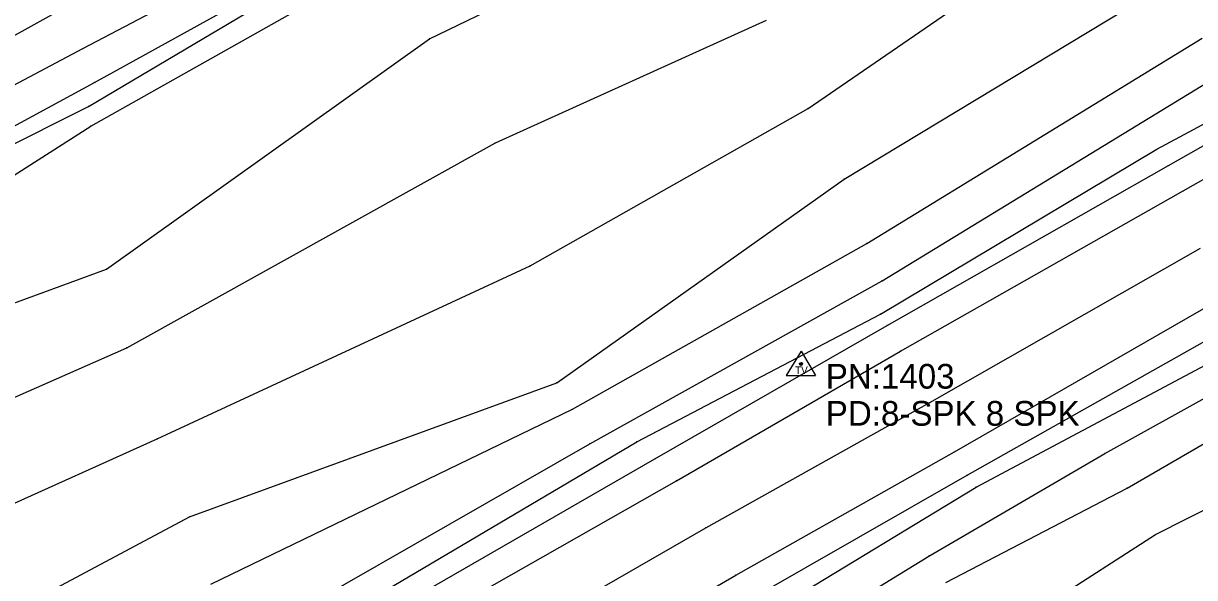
# Model space of a CAD drawing. Extents: x 1419505 to 1434054, y 1956910 to 1968644.
# Drawn here: x 1419625.5 to 1419862.1, y 1957056.8 to 1957168.8 of the extents above; entities that cross this region are included whole.
import ezdxf

# ---------------------------------------------------------------- set-up
doc = ezdxf.new("R2010")
doc.units = 0
for name, color, linetype in [('S_BREAKLINE', 7, 'Continuous'), ('S_DITCHLINE', 7, 'Continuous'), ('S_EDGE_PAVEMENT', 7, 'Continuous'), ('S_GRD_PT_SYM', 7, 'Continuous'), ('S_PAVEMENT_CROWN', 7, 'Continuous'), ('S_RDW_PT_SYM', 7, 'Continuous'), ('S_SECONDARY_CTL', 7, 'Continuous'), ('S_SECONDARY_CTL_ANNOT', 7, 'Continuous'), ('S_SHOULDER', 7, 'Continuous')]:
    doc.layers.add(name, color=color, linetype=linetype)

msp = doc.modelspace()

# ---------------------------------------------------------------- linework, layer by layer
at = {"layer": 'S_BREAKLINE'}
for p, q in [((1419707.5523, 1957165.7068), (1419766.4661, 1957194.2126)), ((1419784.0202, 1957151.5969), (1419847.2843, 1957195.1117)), ((1419637.5618, 1957163.7107), (1419691.7063, 1957192.3615)), ((1419639.1459, 1957148.0477), (1419697.3476, 1957180.8438)), ((1419564.7571, 1957133.6557), (1419643.8152, 1957177.5796)), ((1419791.3307, 1957137.332), (1419859.2891, 1957178.4016)), ((1419720.9172, 1957144.6574), (1419775.6307, 1957169.476)), ((1419854.5158, 1957143.3884), (1419900.6558, 1957168.211)), ((1419642.2981, 1957119.1268), (1419707.5523, 1957165.7068)), ((1419795.917, 1957124.3391), (1419863.6694, 1957165.8298)), ((1419562.865, 1957124.2821), (1419637.5618, 1957163.7107)), ((1419799.0002, 1957116.8016), (1419868.6507, 1957159.3284)), ((1419727.8786, 1957119.8018), (1419784.0202, 1957151.5969)), ((1419579.448, 1957109.9562), (1419639.1459, 1957148.0477)), ((1419646.4093, 1957103.2218), (1419720.9172, 1957144.6574)), ((1419798.6452, 1957110.0602), (1419854.5158, 1957143.3884)), ((1419733.296, 1957096.1553), (1419791.3307, 1957137.332)), ((1419736.4682, 1957090.83), (1419795.917, 1957124.3391)), ((1419652.5397, 1957084.7986), (1419727.8786, 1957119.8018)), ((1419581.6462, 1957096.9554), (1419642.2981, 1957119.1268)), ((1419739.9154, 1957083.8165), (1419799.0002, 1957116.8016)), ((1419843.9531, 1957081.8294), (1419898.0706, 1957111.9563)), ((1419749.447, 1957084.2115), (1419798.6452, 1957110.0602)), ((1419594.165, 1957080.1863), (1419646.4093, 1957103.2218)), ((1419848.5054, 1957074.8589), (1419900.3037, 1957104.9299)), ((1419817.9884, 1957075.058), (1419869.3807, 1957102.4977)), ((1419659.0462, 1957069.0646), (1419733.296, 1957096.1553)), ((1419854.2418, 1957065.4553), (1419906.1381, 1957092.025)), ((1419663.4064, 1957055.4547), (1419736.4682, 1957090.83)), ((1419610.414, 1957065.8034), (1419652.5397, 1957084.7986)), ((1419692.1763, 1957050.3554), (1419749.447, 1957084.2115)), ((1419668.0437, 1957042.6419), (1419739.9154, 1957083.8165)), ((1419808.4198, 1957061.097), (1419843.9531, 1957081.8294)), ((1419773.6516, 1957048.1512), (1419817.9884, 1957075.058)), ((1419811.874, 1957055.7677), (1419848.5054, 1957074.8589)), ((1419622.4238, 1957049.4993), (1419659.0462, 1957069.0646)), ((1419819.8215, 1957043.3979), (1419854.2418, 1957065.4553)), ((1419773.3415, 1957039.6207), (1419808.4198, 1957061.097))]:
    msp.add_line(p, q, dxfattribs=at)
at = {"layer": 'S_DITCHLINE'}
for p, q in [((1419638.6598, 1957151.9969), (1419697.7777, 1957187.1132)), ((1419639.8549, 1957156.8702), (1419695.8855, 1957187.8332)), ((1419570.8935, 1957119.4708), (1419639.8549, 1957156.8702)), ((1419577.5279, 1957121.3749), (1419638.6598, 1957151.9969))]:
    msp.add_line(p, q, dxfattribs=at)
at = {"layer": 'S_EDGE_PAVEMENT'}
for p, q in [((1419859.8281, 1957134.9358), (1419904.819, 1957160.9415)), ((1419802.6874, 1957102.5727), (1419859.8281, 1957134.9358)), ((1419813.6421, 1957082.2014), (1419866.2125, 1957112.4424)), ((1419757.4445, 1957076.345), (1419802.6874, 1957102.5727)), ((1419769.4263, 1957057.2438), (1419813.6421, 1957082.2014)), ((1419697.4796, 1957042.2308), (1419757.4445, 1957076.345)), ((1419709.3334, 1957022.4906), (1419769.4263, 1957057.2438))]:
    msp.add_line(p, q, dxfattribs=at)
at = {"layer": 'S_GRD_PT_SYM'}
for points in [[(1419707.5523, 1957165.7068), (1419707.5523, 1957165.7568), (1419707.5523, 1957165.7068), (1419707.5023, 1957165.7068), (1419707.5523, 1957165.7068), (1419707.5523, 1957165.6568), (1419707.5523, 1957165.7068), (1419707.6023, 1957165.7068)], [(1419637.5618, 1957163.7107), (1419637.5618, 1957163.7607), (1419637.5618, 1957163.7107), (1419637.5118, 1957163.7107), (1419637.5618, 1957163.7107), (1419637.5618, 1957163.6607), (1419637.5618, 1957163.7107), (1419637.6118, 1957163.7107)], [(1419639.8549, 1957156.8702), (1419639.8549, 1957156.9202), (1419639.8549, 1957156.8702), (1419639.8049, 1957156.8702), (1419639.8549, 1957156.8702), (1419639.8549, 1957156.8202), (1419639.8549, 1957156.8702), (1419639.9049, 1957156.8702)], [(1419638.6598, 1957151.9969), (1419638.6598, 1957152.0469), (1419638.6598, 1957151.9969), (1419638.6098, 1957151.9969), (1419638.6598, 1957151.9969), (1419638.6598, 1957151.9469), (1419638.6598, 1957151.9969), (1419638.7098, 1957151.9969)], [(1419784.0202, 1957151.5969), (1419784.0202, 1957151.6469), (1419784.0202, 1957151.5969), (1419783.9702, 1957151.5969), (1419784.0202, 1957151.5969), (1419784.0202, 1957151.5469), (1419784.0202, 1957151.5969), (1419784.0702, 1957151.5969)], [(1419639.1459, 1957148.0477), (1419639.1459, 1957148.0977), (1419639.1459, 1957148.0477), (1419639.0959, 1957148.0477), (1419639.1459, 1957148.0477), (1419639.1459, 1957147.9977), (1419639.1459, 1957148.0477), (1419639.1959, 1957148.0477)], [(1419720.9172, 1957144.6574), (1419720.9172, 1957144.7074), (1419720.9172, 1957144.6574), (1419720.8672, 1957144.6574), (1419720.9172, 1957144.6574), (1419720.9172, 1957144.6074), (1419720.9172, 1957144.6574), (1419720.9672, 1957144.6574)], [(1419854.5158, 1957143.3884), (1419854.5158, 1957143.4384), (1419854.5158, 1957143.3884), (1419854.4658, 1957143.3884), (1419854.5158, 1957143.3884), (1419854.5158, 1957143.3384), (1419854.5158, 1957143.3884), (1419854.5658, 1957143.3884)], [(1419791.3307, 1957137.332), (1419791.3307, 1957137.382), (1419791.3307, 1957137.332), (1419791.2807, 1957137.332), (1419791.3307, 1957137.332), (1419791.3307, 1957137.282), (1419791.3307, 1957137.332), (1419791.3807, 1957137.332)], [(1419795.917, 1957124.3391), (1419795.917, 1957124.3891), (1419795.917, 1957124.3391), (1419795.867, 1957124.3391), (1419795.917, 1957124.3391), (1419795.917, 1957124.2891), (1419795.917, 1957124.3391), (1419795.967, 1957124.3391)], [(1419727.8786, 1957119.8018), (1419727.8786, 1957119.8518), (1419727.8786, 1957119.8018), (1419727.8286, 1957119.8018), (1419727.8786, 1957119.8018), (1419727.8786, 1957119.7518), (1419727.8786, 1957119.8018), (1419727.9286, 1957119.8018)], [(1419642.2981, 1957119.1268), (1419642.2981, 1957119.1768), (1419642.2981, 1957119.1268), (1419642.2481, 1957119.1268), (1419642.2981, 1957119.1268), (1419642.2981, 1957119.0768), (1419642.2981, 1957119.1268), (1419642.3481, 1957119.1268)], [(1419799.0002, 1957116.8016), (1419799.0002, 1957116.8516), (1419799.0002, 1957116.8016), (1419798.9502, 1957116.8016), (1419799.0002, 1957116.8016), (1419799.0002, 1957116.7516), (1419799.0002, 1957116.8016), (1419799.0502, 1957116.8016)], [(1419798.6452, 1957110.0602), (1419798.6452, 1957110.1102), (1419798.6452, 1957110.0602), (1419798.5952, 1957110.0602), (1419798.6452, 1957110.0602), (1419798.6452, 1957110.0102), (1419798.6452, 1957110.0602), (1419798.6952, 1957110.0602)], [(1419646.4093, 1957103.2218), (1419646.4093, 1957103.2718), (1419646.4093, 1957103.2218), (1419646.3593, 1957103.2218), (1419646.4093, 1957103.2218), (1419646.4093, 1957103.1718), (1419646.4093, 1957103.2218), (1419646.4593, 1957103.2218)], [(1419733.296, 1957096.1553), (1419733.296, 1957096.2053), (1419733.296, 1957096.1553), (1419733.246, 1957096.1553), (1419733.296, 1957096.1553), (1419733.296, 1957096.1053), (1419733.296, 1957096.1553), (1419733.346, 1957096.1553)], [(1419736.4682, 1957090.83), (1419736.4682, 1957090.88), (1419736.4682, 1957090.83), (1419736.4182, 1957090.83), (1419736.4682, 1957090.83), (1419736.4682, 1957090.78), (1419736.4682, 1957090.83), (1419736.5182, 1957090.83)], [(1419652.5397, 1957084.7986), (1419652.5397, 1957084.8486), (1419652.5397, 1957084.7986), (1419652.4897, 1957084.7986), (1419652.5397, 1957084.7986), (1419652.5397, 1957084.7486), (1419652.5397, 1957084.7986), (1419652.5897, 1957084.7986)], [(1419749.447, 1957084.2115), (1419749.447, 1957084.2615), (1419749.447, 1957084.2115), (1419749.397, 1957084.2115), (1419749.447, 1957084.2115), (1419749.447, 1957084.1615), (1419749.447, 1957084.2115), (1419749.497, 1957084.2115)], [(1419739.9154, 1957083.8165), (1419739.9154, 1957083.8665), (1419739.9154, 1957083.8165), (1419739.8654, 1957083.8165), (1419739.9154, 1957083.8165), (1419739.9154, 1957083.7665), (1419739.9154, 1957083.8165), (1419739.9654, 1957083.8165)], [(1419843.9531, 1957081.8294), (1419843.9531, 1957081.8794), (1419843.9531, 1957081.8294), (1419843.9031, 1957081.8294), (1419843.9531, 1957081.8294), (1419843.9531, 1957081.7794), (1419843.9531, 1957081.8294), (1419844.0031, 1957081.8294)], [(1419817.9884, 1957075.058), (1419817.9884, 1957075.108), (1419817.9884, 1957075.058), (1419817.9384, 1957075.058), (1419817.9884, 1957075.058), (1419817.9884, 1957075.008), (1419817.9884, 1957075.058), (1419818.0384, 1957075.058)], [(1419848.5054, 1957074.8589), (1419848.5054, 1957074.9089), (1419848.5054, 1957074.8589), (1419848.4554, 1957074.8589), (1419848.5054, 1957074.8589), (1419848.5054, 1957074.8089), (1419848.5054, 1957074.8589), (1419848.5554, 1957074.8589)], [(1419659.0462, 1957069.0646), (1419659.0462, 1957069.1146), (1419659.0462, 1957069.0646), (1419658.9962, 1957069.0646), (1419659.0462, 1957069.0646), (1419659.0462, 1957069.0146), (1419659.0462, 1957069.0646), (1419659.0962, 1957069.0646)], [(1419854.2418, 1957065.4553), (1419854.2418, 1957065.5053), (1419854.2418, 1957065.4553), (1419854.1918, 1957065.4553), (1419854.2418, 1957065.4553), (1419854.2418, 1957065.4053), (1419854.2418, 1957065.4553), (1419854.2918, 1957065.4553)], [(1419808.4198, 1957061.097), (1419808.4198, 1957061.147), (1419808.4198, 1957061.097), (1419808.3698, 1957061.097), (1419808.4198, 1957061.097), (1419808.4198, 1957061.047), (1419808.4198, 1957061.097), (1419808.4698, 1957061.097)]]:
    msp.add_lwpolyline(points, dxfattribs=at)
at = {"layer": 'S_PAVEMENT_CROWN'}
for p, q in [((1419808.6528, 1957092.1611), (1419863.2824, 1957123.3621)), ((1419763.3489, 1957066.8294), (1419808.6528, 1957092.1611)), ((1419703.035, 1957032.1262), (1419763.3489, 1957066.8294))]:
    msp.add_line(p, q, dxfattribs=at)
at = {"layer": 'S_RDW_PT_SYM'}
for points in [[(1419856.8619, 1957140.1122), (1419856.8619, 1957140.1622), (1419856.8619, 1957140.1122), (1419856.8119, 1957140.1122), (1419856.8619, 1957140.1122), (1419856.8619, 1957140.0622), (1419856.8619, 1957140.1122), (1419856.9119, 1957140.1122)], [(1419859.8281, 1957134.9358), (1419859.8281, 1957134.9858), (1419859.8281, 1957134.9358), (1419859.7781, 1957134.9358), (1419859.8281, 1957134.9358), (1419859.8281, 1957134.8858), (1419859.8281, 1957134.9358), (1419859.8781, 1957134.9358)], [(1419799.9863, 1957107.7121), (1419799.9863, 1957107.7621), (1419799.9863, 1957107.7121), (1419799.9363, 1957107.7121), (1419799.9863, 1957107.7121), (1419799.9863, 1957107.6621), (1419799.9863, 1957107.7121), (1419800.0363, 1957107.7121)], [(1419802.6874, 1957102.5727), (1419802.6874, 1957102.6227), (1419802.6874, 1957102.5727), (1419802.6374, 1957102.5727), (1419802.6874, 1957102.5727), (1419802.6874, 1957102.5227), (1419802.6874, 1957102.5727), (1419802.7374, 1957102.5727)], [(1419808.6528, 1957092.1611), (1419808.6528, 1957092.2111), (1419808.6528, 1957092.1611), (1419808.6028, 1957092.1611), (1419808.6528, 1957092.1611), (1419808.6528, 1957092.1111), (1419808.6528, 1957092.1611), (1419808.7028, 1957092.1611)], [(1419813.6421, 1957082.2014), (1419813.6421, 1957082.2514), (1419813.6421, 1957082.2014), (1419813.5921, 1957082.2014), (1419813.6421, 1957082.2014), (1419813.6421, 1957082.1514), (1419813.6421, 1957082.2014), (1419813.6921, 1957082.2014)], [(1419753.0952, 1957080.7723), (1419753.0952, 1957080.8223), (1419753.0952, 1957080.7723), (1419753.0452, 1957080.7723), (1419753.0952, 1957080.7723), (1419753.0952, 1957080.7223), (1419753.0952, 1957080.7723), (1419753.1452, 1957080.7723)], [(1419816.1713, 1957077.4441), (1419816.1713, 1957077.4941), (1419816.1713, 1957077.4441), (1419816.1213, 1957077.4441), (1419816.1713, 1957077.4441), (1419816.1713, 1957077.3941), (1419816.1713, 1957077.4441), (1419816.2213, 1957077.4441)], [(1419757.4445, 1957076.345), (1419757.4445, 1957076.395), (1419757.4445, 1957076.345), (1419757.3945, 1957076.345), (1419757.4445, 1957076.345), (1419757.4445, 1957076.295), (1419757.4445, 1957076.345), (1419757.4945, 1957076.345)], [(1419763.3489, 1957066.8294), (1419763.3489, 1957066.8794), (1419763.3489, 1957066.8294), (1419763.2989, 1957066.8294), (1419763.3489, 1957066.8294), (1419763.3489, 1957066.7794), (1419763.3489, 1957066.8294), (1419763.3989, 1957066.8294)], [(1419769.4263, 1957057.2438), (1419769.4263, 1957057.2938), (1419769.4263, 1957057.2438), (1419769.3763, 1957057.2438), (1419769.4263, 1957057.2438), (1419769.4263, 1957057.1938), (1419769.4263, 1957057.2438), (1419769.4763, 1957057.2438)]]:
    msp.add_lwpolyline(points, dxfattribs=at)
at = {"layer": 'S_SECONDARY_CTL'}
for p, q in [((1419782.6111, 1957102.5817), (1419779.6011, 1957097.6278)), ((1419782.6111, 1957102.5817), (1419785.5584, 1957097.6278)), ((1419779.6011, 1957097.6278), (1419785.5584, 1957097.6278))]:
    msp.add_line(p, q, dxfattribs=at)
for radius in [0.3111, 0.1827, 0.1033]:
    msp.add_circle((1419782.6111, 1957099.9716), radius, dxfattribs=at)
at = {"layer": 'S_SHOULDER'}
for p, q in [((1419856.8619, 1957140.1122), (1419901.9028, 1957165.6538)), ((1419799.9863, 1957107.7121), (1419856.8619, 1957140.1122)), ((1419753.0952, 1957080.7723), (1419799.9863, 1957107.7121)), ((1419816.1713, 1957077.4441), (1419867.7046, 1957106.598)), ((1419694.5665, 1957047.0731), (1419753.0952, 1957080.7723)), ((1419772.3745, 1957052.4325), (1419816.1713, 1957077.4441))]:
    msp.add_line(p, q, dxfattribs=at)

# ---------------------------------------------------------------- texts
at = {"layer": 'S_SECONDARY_CTL'}
msp.add_text('TV', height=1.5, rotation=360, dxfattribs=at).set_placement((1419781.4064, 1957097.9603))
at = {"layer": 'S_SECONDARY_CTL_ANNOT'}
for s, p in [('PN:1403', (1419787.6111, 1957094.9716)), ('PD:8-SPK 8 SPK', (1419787.6111, 1957087.4716))]:
    msp.add_text(s, height=5, dxfattribs=at).set_placement(p)

doc.saveas('drawing.dxf')
